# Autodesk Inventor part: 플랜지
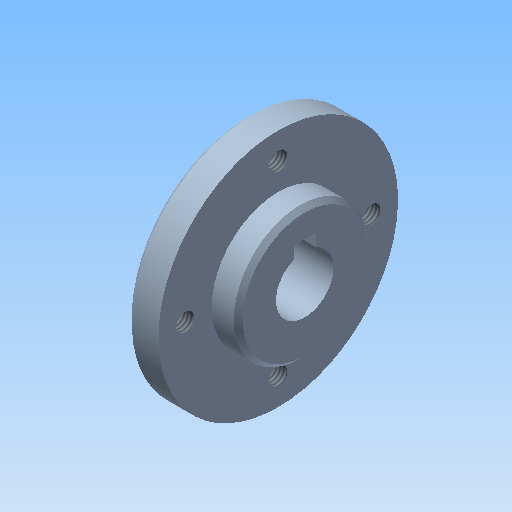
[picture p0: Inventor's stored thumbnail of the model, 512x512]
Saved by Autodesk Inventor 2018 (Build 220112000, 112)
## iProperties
Created: 2024-02
Part Number: 플랜지
Material: 강철, 탄소
Document SubType Name: Modeling
Designer: mdu-01
Density: 1 g/cm^3
Appearance: 기본값(1)
Author: mdu-01
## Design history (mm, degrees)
sketch "스케치1"
  geometry: L1 (0, 0)-(22, 0); L2 (0, -6.5)-(0, -11); L3 (0, -11)-(9, -11); L4 (9, -11)-(9, -26); L5 (10, -27)-(16, -27); L6 (16, -27)-(16, -15); L7 (16, -15)-(21, -15); L8 (22, -14)-(22, -6.5); L9 (22, -6.5)-(0, -6.5); L10 (21, -15)-(22, -14); L11 (9, -26)-(10, -27); L12 (0, 0)-(0, 8.8); L13 (0, 8.8)-(22, 8.8); L14 (22, 8.8)-(22, 0); 2 further points
  constraints: 28 end point, 6 parallel, 6 point on line, 4 perpendicular, 1 horizontal, 1 vertical
  dimensions: "d0" = 22 distance of L1.start L1.end; "d1" = 54 diameter of L5 L1; "d2" = 22 diameter of L3 L1; "d3" = 13 diameter of L9 L1; "d4" = 9 distance between parallel lines of L4 L2; "d5" = 6 distance between parallel lines of L8 L6; "d6" = 30 diameter of L7 L1; "d7" = 1 distance of L7.end point (22, -15); "d8" = 1 distance of L8.start point (22, -15) (= d7); "d9" = 1 distance of L4.end point (9, -27) (= d7); "d10" = 1 distance of L5.start point (9, -27) (= d9); "d11" = 15.3 distance between parallel lines of L13 L9
revolve "회전1" stored, may be unused: angle "d12" = 90 deg
extrude "돌출1" cut sketch "스케치1" stored distance "d13" = 5; taper "d14" = 0 deg
chamfer "모따기1" distance "d15" = 1; stored, may be unused: second distance "d16" = 2, angle "d17" = 45 deg
sketch "스케치2" dims "d18" = 42
  geometry: 3 further points
  constraints: 2 vertical alignment, 1 coincident, 2 other
hole "구멍1" sketch "스케치2" at (0, 21) diameter "d20" = 4.134; stored, may be unused: countersink angle "d24" = 90 deg, drill point angle "d26" = 118 deg; dims "d21" = 6, "d22" = 4, "d23" = 2, "d25" = 8
node "솔리드1"
pattern_circular "원형 패턴1" dims angle "d28" = 360 deg
